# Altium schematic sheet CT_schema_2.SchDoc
size 271 x 229 mm
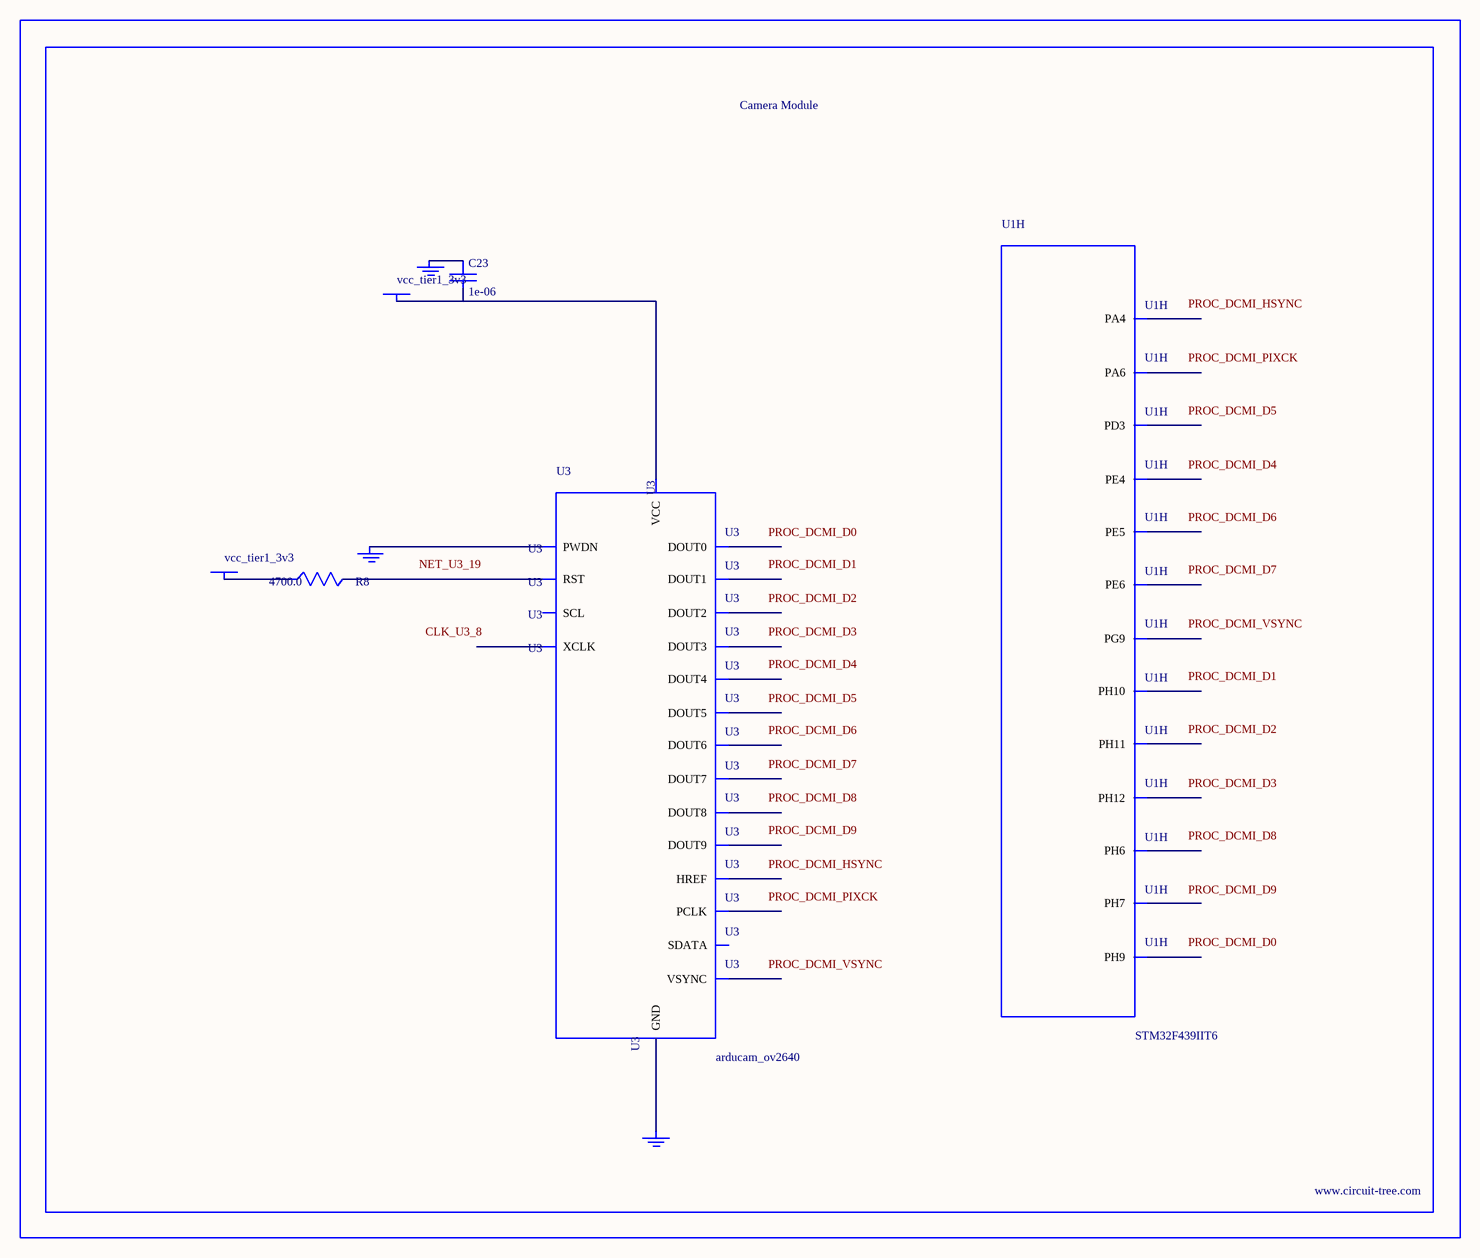
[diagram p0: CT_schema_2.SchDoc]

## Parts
BORDER1  (no value)
C23  1e-06  [C0603]
GND_INSTANCE_1_0  (no value)
GND_INSTANCE_1_1  (no value)
GND_INSTANCE_1_2  (no value)
POWER_INSTANCE_1_0  vcc_tier1_3v3
POWER_INSTANCE_1_1  vcc_tier1_3v3
R8  4700.0  [R0603]
U1  STM32F439IIT6  [LQFP176]  (part H of 11)
U3  arducam_ov2640  [ARDUCAM]

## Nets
NetC23_1: C23.1 GND_INSTANCE_1_0.0(GND)
NetC23_2: C23.2 POWER_INSTANCE_1_0.0(PWR) U3.1(VCC)
NetGND_INSTANCE_1_1_0: GND_INSTANCE_1_1.0(GND) U3.20(PWDN)
NetGND_INSTANCE_1_2_0: GND_INSTANCE_1_2.0(GND) U3.2(GND)
NetPOWER_INSTANCE_1_1_0: POWER_INSTANCE_1_1.0(PWR) R8.1
NetR8_2: R8.2 U3.19(RST)

Not connected (* = marked no-connect by the designer): U1 3(PE4) 4(PE5) 5(PE6) 50(PA4) 52(PA6) 83(PH6) 84(PH7) 86(PH9) 87(PH10) 88(PH11) 89(PH12) 145(PD3) 152(PG9); U3 3(SCL) 4(SDATA) 5(VSYNC) 6(HREF) 7(PCLK) 8(XCLK) 9(DOUT9) 10(DOUT8) 11(DOUT7) 12(DOUT6) 13(DOUT5) 14(DOUT4) 15(DOUT3) 16(DOUT2) 17(DOUT1) 18(DOUT0)

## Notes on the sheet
- Labels drawn without touching a wire or pin: CLK_U3_8, NET_U3_19, PROC_DCMI_D0, PROC_DCMI_D1, PROC_DCMI_D2, PROC_DCMI_D3, PROC_DCMI_D4, PROC_DCMI_D5, PROC_DCMI_D6, PROC_DCMI_D7, PROC_DCMI_D8, PROC_DCMI_D9, PROC_DCMI_HSYNC, PROC_DCMI_PIXCK, PROC_DCMI_VSYNC

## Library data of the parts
BORDER1 = BORDER_PAGE1
C23 = C0603C105K3RACTU
GND_INSTANCE_1_0-GND_INSTANCE_1_2 = GND
POWER_INSTANCE_1_0 POWER_INSTANCE_1_1 = PWR
R8 = RC0603JR-074K7L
